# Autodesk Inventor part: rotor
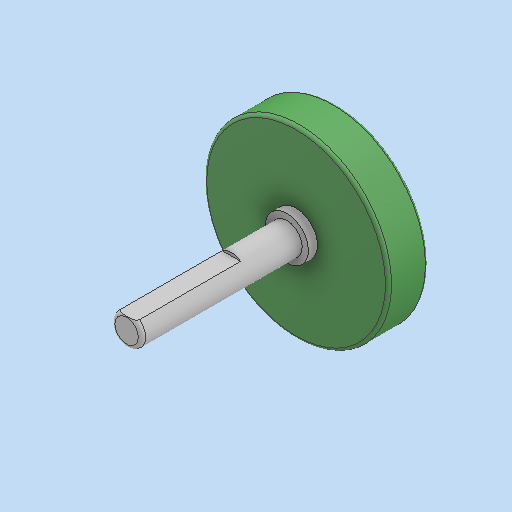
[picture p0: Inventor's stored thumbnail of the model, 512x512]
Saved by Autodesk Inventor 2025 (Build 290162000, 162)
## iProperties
Created: 2025-05
Part Number: rotor
Material: Generico
Description: rotor
Document SubType Name: Modeling
Designer: R5800u
Density: 1 g/cm^3
Appearance: Default
Author: R5800u
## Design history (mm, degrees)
feature "Base1"
node "Solido1"
